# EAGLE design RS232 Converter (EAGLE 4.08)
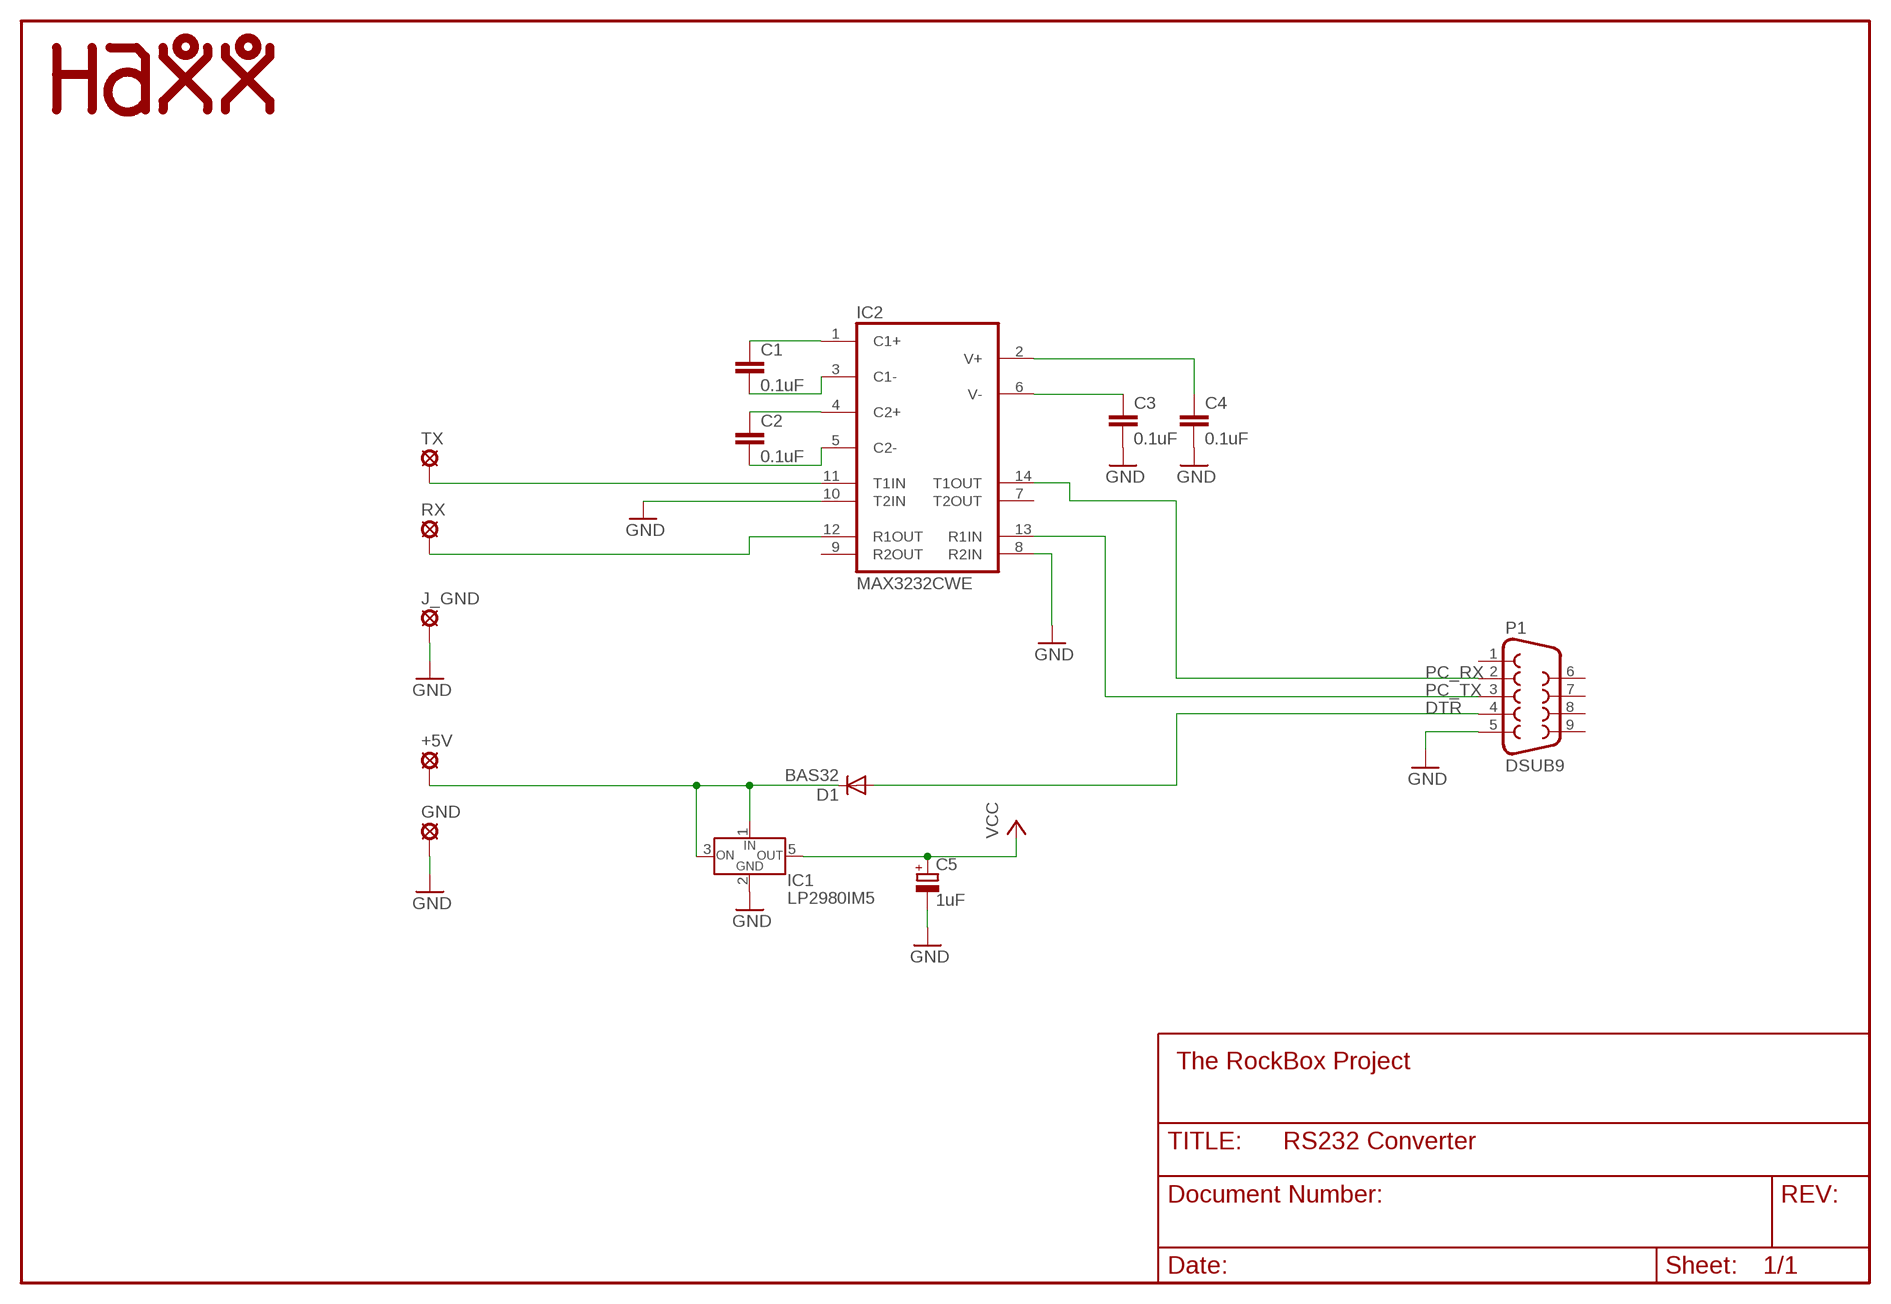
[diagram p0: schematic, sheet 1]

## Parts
+5V  LSP10  [LSP10]
C1  0.1uF  C-EUC0805  [C0805]
C2  0.1uF  C-EUC0805  [C0805]
C3  0.1uF  C-EUC0805  [C0805]
C4  0.1uF  C-EUC0805  [C0805]
C5  1uF  CPOL-EUCT3216  [CT3216]
D1  BAS32  DIODE-SOD80C  [SOD80C]
GND  LSP10  [LSP10]
IC1  LP2980IM5  [SOT23-5]
IC2  MAX3232CWE  [SO16]
J_GND  LSP10  [LSP10]
P1  DSUB9  [DSUB9]
RX  LSP10  [LSP10]
TX  LSP10  [LSP10]
U$1  HAXX  [HAXX]

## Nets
DTR: D1.A P1.4
GND: C3.2 C4.2 C5.- GND.MP IC1.2(GND) IC2.8(R2IN) IC2.10(T2IN) J_GND.MP P1.5
N$1: C1.1 IC2.1(C1+)
N$2: C1.2 IC2.3(C1-)
N$3: C2.1 IC2.4(C2+)
N$4: C2.2 IC2.5(C2-)
N$5: IC2.12(R1OUT) RX.MP
N$6: C3.1 IC2.6(V-)
N$7: C4.1 IC2.2(V+)
N$8: +5V.MP D1.C IC1.1(IN) IC1.3(ON/OFF)
N$9: IC2.11(T1IN) TX.MP
PC_RX: IC2.14(T1OUT) P1.2
PC_TX: IC2.13(R1IN) P1.3
VCC: C5.+ IC1.5(OUT)
Unconnected: IC2.7(T2OUT) IC2.9(R2OUT) P1.1 P1.6 P1.7 P1.8 P1.9

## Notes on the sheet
- The RockBox Project

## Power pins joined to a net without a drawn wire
GND: IC2.15(GND)
VCC: IC2.16(VCC)

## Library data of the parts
+5V GND J_GND RX TX = solpad:LSP10: SOLDER PAD
C1-C4 = rcl:C-EU: CAPACITOR, European symbol
C5 = rcl:CPOL-EU: POLARIZED CAPACITOR, European symbol
D1 = diode:DIODE-: DIODE
IC1 = linus:LP2980IM5
IC2 = maxim:MAX3232: RS232 TRANSEIVER
P1 = linus:DSUB9
U$1 = linus:HAXX

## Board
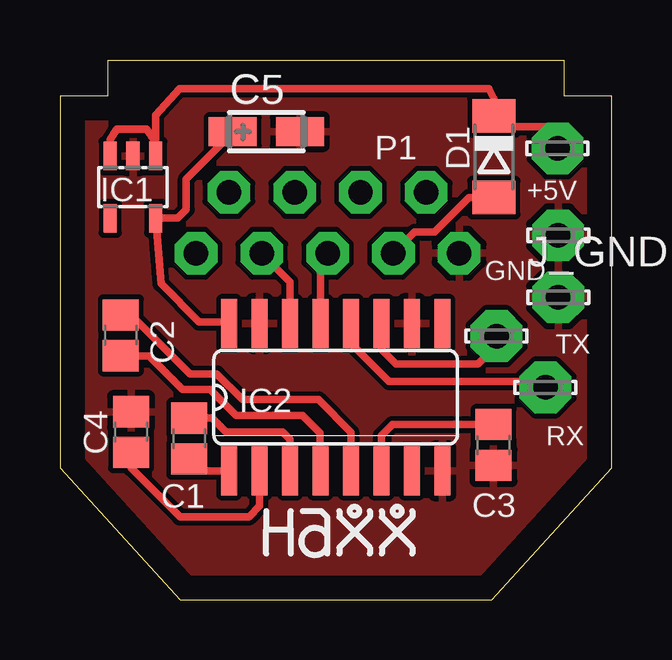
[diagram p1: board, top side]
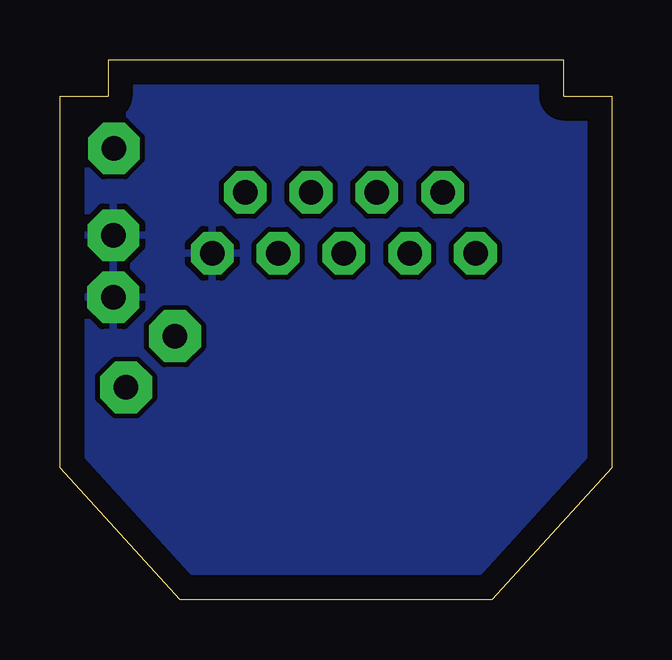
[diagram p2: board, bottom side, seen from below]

Size 23 x 22.5 mm. Coordinates in mm from the lower left corner, seen from the top.
Outline: 0,21 0,5.5 5,0 18,0 23,5.5 23,21 21,21 21,22.5 2,22.5 2,21 0,21
Copper layers used: Top, Bottom

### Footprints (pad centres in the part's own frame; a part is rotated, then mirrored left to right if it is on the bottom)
LSP10 = drill 1.016 pad 2.159 octagon: MP 0,0
C0805 = smd 1.3 x 1.5: 1 -0.85,0; 2 0.85,0
CT3216 = smd 2 x 1.2: + -1.4,0; - 1.4,0
SOD80C = smd 1.4 x 1.8: A 1.7,0; C -1.7,0
SOT23-5 = smd 0.55 x 1.2: 1 -0.95,-1.3; 2 0,-1.3; 3 0.95,-1.3; 4 0.95,1.3; 5 -0.95,1.3
SO16 = smd 0.66 x 2.032: 1 -4.445,-3.073; 2 -3.175,-3.073; 3 -1.905,-3.073; 4 -0.635,-3.073; 5 0.635,-3.073; 6 1.905,-3.073; 7 3.175,-3.073; 8 4.445,-3.073; 9 4.445,3.073; 10 3.175,3.073; 11 1.905,3.073; 12 0.635,3.073; 13 -0.635,3.073; 14 -1.905,3.073; 15 -3.175,3.073; 16 -4.445,3.073
DSUB9 = drill 1.016 pad 1.778 octagon: 1 -5.486,-1.27; 2 -2.743,-1.27; 3 0,-1.27; 4 2.743,-1.27; 5 5.486,-1.27; 6 -4.115,1.27; 7 -1.372,1.27; 8 1.372,1.27; 9 4.115,1.27

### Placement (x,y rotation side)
+5V  20.75,18.81 0 top
C1  5.39,6.71 90 top
C2  2.54,11.02 90 top
C3  18.07,6.45 270 top
C4  2.97,6.98 90 top
C5  8.61,19.51 0 top
D1  18.09,18.47 270 top
GND  20.77,15.19 0 top
IC1  3.04,17.2 180 top
IC2  11.5,8.44 0 top
J_GND  20.78,12.61 0 top
P1  11.16,15.71 0 top
RX  20.24,8.85 0 top
TX  18.2,10.98 0 top
U$1  11.39,2.93 0 top

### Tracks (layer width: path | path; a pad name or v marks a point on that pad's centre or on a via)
DTR
  Top 0.305: D1.A 17.06,16.77 15.61,15.32 14.78,15.32 P1.4
GND
  pour Top: 2.01,22.47 1.98,21 -0.04,21 -0.04,5.54 5.01,0.04 18.04,0.01 23.01,5.58 22.94,21.07 20.93,21 20.93,22.47
  pour Bottom: 0.04,20.96 0.04,5.58 -0.04,5.51 -0.04,5.02 5.08,-0.09 17.89,-0.09 17.99,0.02 17.99,0.47 23.07,5.55 23.07,20.86 22.93,21 21.02,21.07 21.02,22.43 19.92,22.54 2.05,22.54 2.05,21.17
N$1
  Top 0.305: C1.1 5.39,5.72 5.74,5.37 6.96,5.37 7,5.41 IC2.1
N$2
  Top 0.305: C1.2 6.35,7.56 6.93,6.98 9.28,6.98 9.59,6.67 9.59,5.41 9.63,5.37 9.62,5.36 IC2.3
N$3
  Top 0.305: C2.1 3.71,10.17 5.11,8.77 6.26,8.77 7.35,7.68 10.12,7.68 10.85,6.95 10.85,5.41 10.9,5.36 | 10.9,5.36 10.96,5.3 | 10.9,5.36 IC2.4
N$4
  Top 0.305: C2.2 2.97,11.86 5.42,9.41 6.54,9.41 7.61,8.34 10.77,8.34 12.13,6.98 12.13,5.4 12.17,5.36 | 12.17,5.36 12.18,5.35 | 12.17,5.36 IC2.5
N$5
  Top 0.305: IC2.12 12.13,10.67 13.72,9.08 19.88,9.08 19.92,9.12 19.94,9.1 RX.MP
N$6
  Top 0.305: IC2.6 13.4,6.84 13.86,7.3 17.99,7.3 18.07,7.22 | 18.07,7.22 18.13,7.16 | 18.07,7.22 C3.1
N$7
  Top 0.305: C4.1 2.97,5.48 5,3.45 7.88,3.45 8.33,3.9 8.33,5.27 8.32,5.28 IC2.2
N$8
  Top 0.305: +5V.MP 20.37,19.56 20.37,19.72 18.95,19.72 D1.C 18.09,20.88 17.88,21.3 4.98,21.3 3.98,20.2 3.98,18.44 3.99,18.45 IC1.1 3.99,19.08 3.61,19.62 2.36,19.62 2.09,19.18 2.09,18.68 2.11,18.66 2.09,18.64 IC1.3
N$9
  Top 0.305: IC2.11 13.4,10.42 14,9.82 17.43,9.82 18.2,10.59 TX.MP
PC_RX
  Top 0.305: P1.2 8.42,14.42 8.41,14.42 9.59,13.24 IC2.14
PC_TX
  Top 0.305: IC2.13 10.87,12.5 10.87,13.57 P1.3
VCC
  Top 0.305: IC2.16 7.07,11.53 7.04,11.57 5.81,11.57 4.21,13.17 IC1.5 4.91,15.9 5.27,16.26 5.27,17.53 7.25,19.5 7.24,19.51 C5.+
